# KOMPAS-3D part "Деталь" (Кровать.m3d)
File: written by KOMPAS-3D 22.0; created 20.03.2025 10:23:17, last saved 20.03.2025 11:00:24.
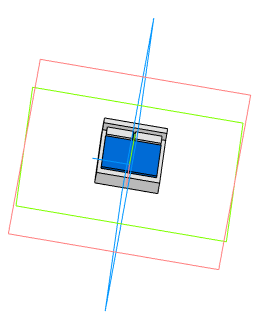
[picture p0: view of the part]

Document properties: Автор: Пользователь Windows; Полное имя файла: C:\Users\Student\Documents\Картошечка\База Сабнатика\Мебель\Кровать.m3d

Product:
- Body: Тело 1
    Масса: 0.008507
- Part/product: Деталь
    Масса: 0.008517

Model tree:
1. Эскиз:1
2. Элемент выдавливания:1
     Расстояние 1 = 3
3. Эскиз:2  (with: Элемент выдавливания:1)
4. Элемент выдавливания:2
     Расстояние 1 = 2
5. Эскиз:3  (with: Элемент выдавливания:1, Элемент выдавливания:2)
6. Элемент выдавливания:3
     Расстояние 1 = 0.5
7. Эскиз:4  (with: Элемент выдавливания:1, Элемент выдавливания:3)
8. Элемент выдавливания:4
     Расстояние 1 = 1
9. Эскиз:5  (with: Элемент выдавливания:3, Элемент выдавливания:4)
10. Элемент выдавливания:5
     Расстояние 1 = 0.1
11. Зеркальный массив:1
12. Экземпляр ( 1 )
13. Экземпляр ( 2 )  (with: Элемент выдавливания:5)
